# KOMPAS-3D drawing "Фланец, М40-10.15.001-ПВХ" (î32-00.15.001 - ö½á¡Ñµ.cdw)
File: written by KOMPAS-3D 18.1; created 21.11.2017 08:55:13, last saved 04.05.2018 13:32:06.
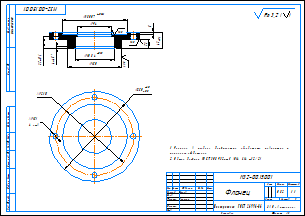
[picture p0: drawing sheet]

Sheet 1: A3, landscape

Document properties: Полное имя файла: D:\Magna\Магна Ins\Магна ins 32\Для Караби\М32-00.15.001 - Фланец.cdw; Масса: 0.816359

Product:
- Part/product: Фланец  | designation М40-10.15.001-ПВХ
    Материал: Полипропилен  ГОСТ 26996-86 (density 900 kg/m3)
    Масса: 0.962205
    Раздел спецификации: Детали
    Форматы листов документа: A3
- Part/product: Переходной фланец  | designation М40-00.15.001
    Материал: Полипропилен  ГОСТ 26996-86 (density 900 kg/m3)
    Масса: 0.815286
    Раздел спецификации: Детали
    Форматы листов документа: A3
- Part/product: Переходной фланец  | designation М40-00.15.002
    Материал: Полипропилен  ГОСТ 26996-86 (density 900 kg/m3)
    Масса: 1.3652
    Раздел спецификации: Детали
    Форматы листов документа: A3
- Part/product: Фланец  | designation М32-00.15.001
    Материал: Полипропилен  ГОСТ 26996-86 (density 900 kg/m3)
    Масса: 0.816359
    Раздел спецификации: Детали
    Форматы листов документа: A3
    source file: М32-00.15.001 - Фланец.cdw

Title block, sheet 1: Наименование: Фланец; designation: М32-00.15.001; Материал: Полипропилен  ГОСТ 26996-86; Масса: 0,82; scale: 1:1; Количество листов документа: 1; organisation: ЗАО «Астерион»; Форматы листов документа: A3; stored path: D:\Отработать\Магна 40\Чертежи\М40-00.15.001 - Фланец.cdw; Разработал: Милов; Т. контр.: Лучихин

Views: Вид 1, Местный разрез 1, Спереди, Проекционный вид 2
Referenced files in Z:\Магна\Магна Ins\Магна ins 32\: М32-00.15.001 - Фланец.m3d
Referenced files in D:\Отработать\Магна 40\3Д\: Фланец.m3d
Referenced files in D:\Magna\Магна Ins\Магна ins 32\Для Караби\: М32-00.15.001 - Фланец.m3d
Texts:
  Ra 3,2
  Ra 3,2 ( )
Dimensions and other numbers on the sheet: 94; 180; 5; 43; 23; 32±0,1; 108,4; 150; 12,5; 4; 250; 215; 15; 4 отв.; 1:1; 1; 0,82

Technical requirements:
  Размеры в скобках допускается обработать совместно с
  сопрягаемой деталью.
  Общие допуски ГОСТ 30893.2-тК (H14, h14,  t2/2).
